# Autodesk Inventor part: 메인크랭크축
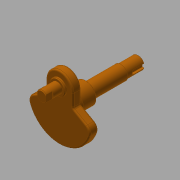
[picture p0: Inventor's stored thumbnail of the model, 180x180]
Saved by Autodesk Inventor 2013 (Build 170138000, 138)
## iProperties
Created: 2016-11
Part Number: 메인크랭크축
Material: 강철, 탄소
Document SubType Name: Modeling
Designer: mduedu
Density: 7.87 g/cm^3
Mass: 807.421 g
Surface Area: 206.102 cm^2
Volume: 102.595 cm^3
Author: mduedu
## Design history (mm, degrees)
sketch "스케치1" dims "d8" = 65
  geometry: L1 (-19, 26.368)-(-19, 8.368); L2 (-19, 8.368)-(-44.545, -6.381); L3 (0, 26.368)-(0, -45); L4 (19, 26.368)-(19, 8.368); L5 (19, 8.368)-(44.545, -6.381); C1 r 10 at (0, 0); C2 r 17.5 at (0, 0); A1 r 45 centre (0, 0) between (-44.545, -6.381) and (0, -45); A2 r 19 centre (0, 26.368) between (0, 45.368) and (-19, 26.368); A3 r 19 centre (0, 26.368) between (19, 26.368) and (0, 45.368); A4 r 45 centre (0, 0) between (0, -45) and (44.545, -6.381); 2 further points
  constraints: 10 end point, 8 point on circle, 6 centre point, 4 coincident, 3 symmetric about line, 2 point on line, 1 parallel, 1 tangent, 1 vertical, 1 vertical alignment, 5 other
  dimensions: "d1" = 20 diameter of C1; "d2" = 35 diameter of C2; "d4" = 18 distance of L1.start L1.end; "d5" = 120 deg angle of L2 L1; "d6" = 45 radius of A1; "d9" = 19 radius of A2
extrude "돌출1" new body sketch "스케치1" distance "d10" = 12; taper "d11" = 0 deg
extrude "돌출2" join sketch "스케치1" distance "d12" = 5; taper "d13" = 0 deg
extrude "돌출3" join sketch "스케치1" distance "d14" = 100; taper "d15" = 0 deg
sketch "스케치2"
  geometry: C1 r 7.5 at (0, 26.368); C2 r 11 at (0, 26.368); A1 r 19 centre (0, 26.368) between (19, 26.368) and (-19, 26.368) reference; 1 further point
  constraints: 2 centre point, 2 coincident
  dimensions: "d16" = 15 diameter of C1; "d17" = 22 diameter of C2
extrude "돌출4" join sketch "스케치2" distance "d18" = 3; taper "d19" = 0 deg
extrude "돌출5" join sketch "스케치2" distance "d20" = 25; taper "d21" = 0 deg
node "작업 평면1"
sketch "스케치3"
  geometry: L1 (-5.75, -4.815)-(5.75, -4.815); L2 (5.75, -4.815)-(5.75, 4.815); L3 (5.75, 4.815)-(-5.75, 4.815); L4 (-5.75, 4.815)-(-5.75, -4.815); L5 (-5.75, -4.815)-(5.75, 4.815); L6 (5.75, -4.815)-(-5.75, 4.815); A1 r 7.5 centre (0, 0) between (-5.75, 4.815) and (-5.75, -4.815); A2 r 7.5 centre (0, 0) between (5.75, -4.815) and (5.75, 4.815); 2 further points
  constraints: 12 end point, 4 point on circle, 2 centre point, 2 midpoint, 2 parallel, 1 coincident, 1 horizontal, 1 perpendicular, 2 other
  dimensions: "d23" = 11.5 distance between parallel lines of L2 L4
extrude "돌출6" cut sketch "스케치3" stored distance "d25" = 25; taper "d26" = 0 deg
fillet "모깎기1" dims "d27" = 3, "d29" = 10
fillet "모깎기2" dims "d28" = 2
sketch "스케치4"
  geometry: C1 r 15 at (0, 0); 1 further point
  constraints: 1 centre point, 1 coincident
  dimensions: "d30" = 30 diameter of C1
extrude "돌출7" join sketch "스케치4" distance "d31" = 21; taper "d32" = 0 deg
sketch "스케치5"
  geometry: C1 r 10 at (0, 0) reference; C2 r 9 at (0, 0); 1 further point
  constraints: 1 centre point
  dimensions: "d33" = 1 radial gap between concentric circles of C1 C2
extrude "돌출8" cut sketch "스케치5" distance "d34" = 25; taper "d35" = 0 deg
node "작업 평면2"
sketch "스케치6"
  geometry: L1 (-9, 0)-(9, 0) reference; L2 (-3, 0)-(3, 0); L3 (3, 0)-(3, 15); L4 (-3, 15)-(-3, 0); A1 r 3 centre (0, 15) between (3, 15) and (-3, 15); 1 further point
  constraints: 6 end point, 2 point on circle, 2 tangent, 1 centre point, 1 horizontal, 1 parallel, 1 perpendicular, 1 point on line, 1 vertical alignment
  dimensions: "d36" = 18 dimension on A1 L1; "d37" = 6 distance between parallel lines of L3 L4
extrude "돌출9" cut sketch "스케치6" distance "d38" = 3.5; taper "d39" = 0 deg
chamfer "모따기1" distance "d40" = 1; stored, may be unused: second distance "d41" = 2, angle "d42" = 45 deg
chamfer "모따기2" distance "d43" = 1; stored, may be unused: second distance "d44" = 2, angle "d45" = 45 deg
node "솔리드1"
node "투영된 루프1"
other parameters: "d3" = 38, "d22" = 13
